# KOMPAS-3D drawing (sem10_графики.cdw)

Referenced files in \\XDEV-LAPTOP\Users\xdev\Desktop\baumanka\sem10\Курсач\pics\: mu.jpg, i.jpg, nu.jpg
Referenced files: sem10_графики.cdw
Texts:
  Автопилот стабилизации угла крена
  Графики
  xdev
  Аппроксимация передаточных чисел АП
  H, км
  i рас
  i кор
  i ап
  Опорный режим - 2
  Параметры АП после аппроксимации:
  Расчетные, скорректированные и аппроксимированные передаточные числа
  H, мх10 3
  Пашинин С.А.
  Окоемов Б.Н.
  МГТУ им. Н. Э. Баумана
  Кафедра ИУ2
  Группа ИУ2-102
Dimensions and other numbers on the sheet: 1; 0; 0,335; 1,534; 0,098; 0,676; 0,527; 0,341; 0,838; 2; 0,033; 3; 0,806; 0,670; 4; 5; 0,737; 2,761; 0,241; 0,077; 1,179; 0,777; 6; 10; 0,354; 1,406; 0,144; 0,660; 7; 0,306; 1,588; 0,058; 0,683; 8; 0,319; 1,698; 0,048; 0,698; 9; 15; 0,898; 3,047; 0,870; 11; 12; 20; 0,735; 0,598; 1,995; 2,744; 2,250; 6,429; 0,243; 0,209; 0,566; 0,826; 0,769; 1,087; 1:1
